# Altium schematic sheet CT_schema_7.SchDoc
size 405 x 220 mm
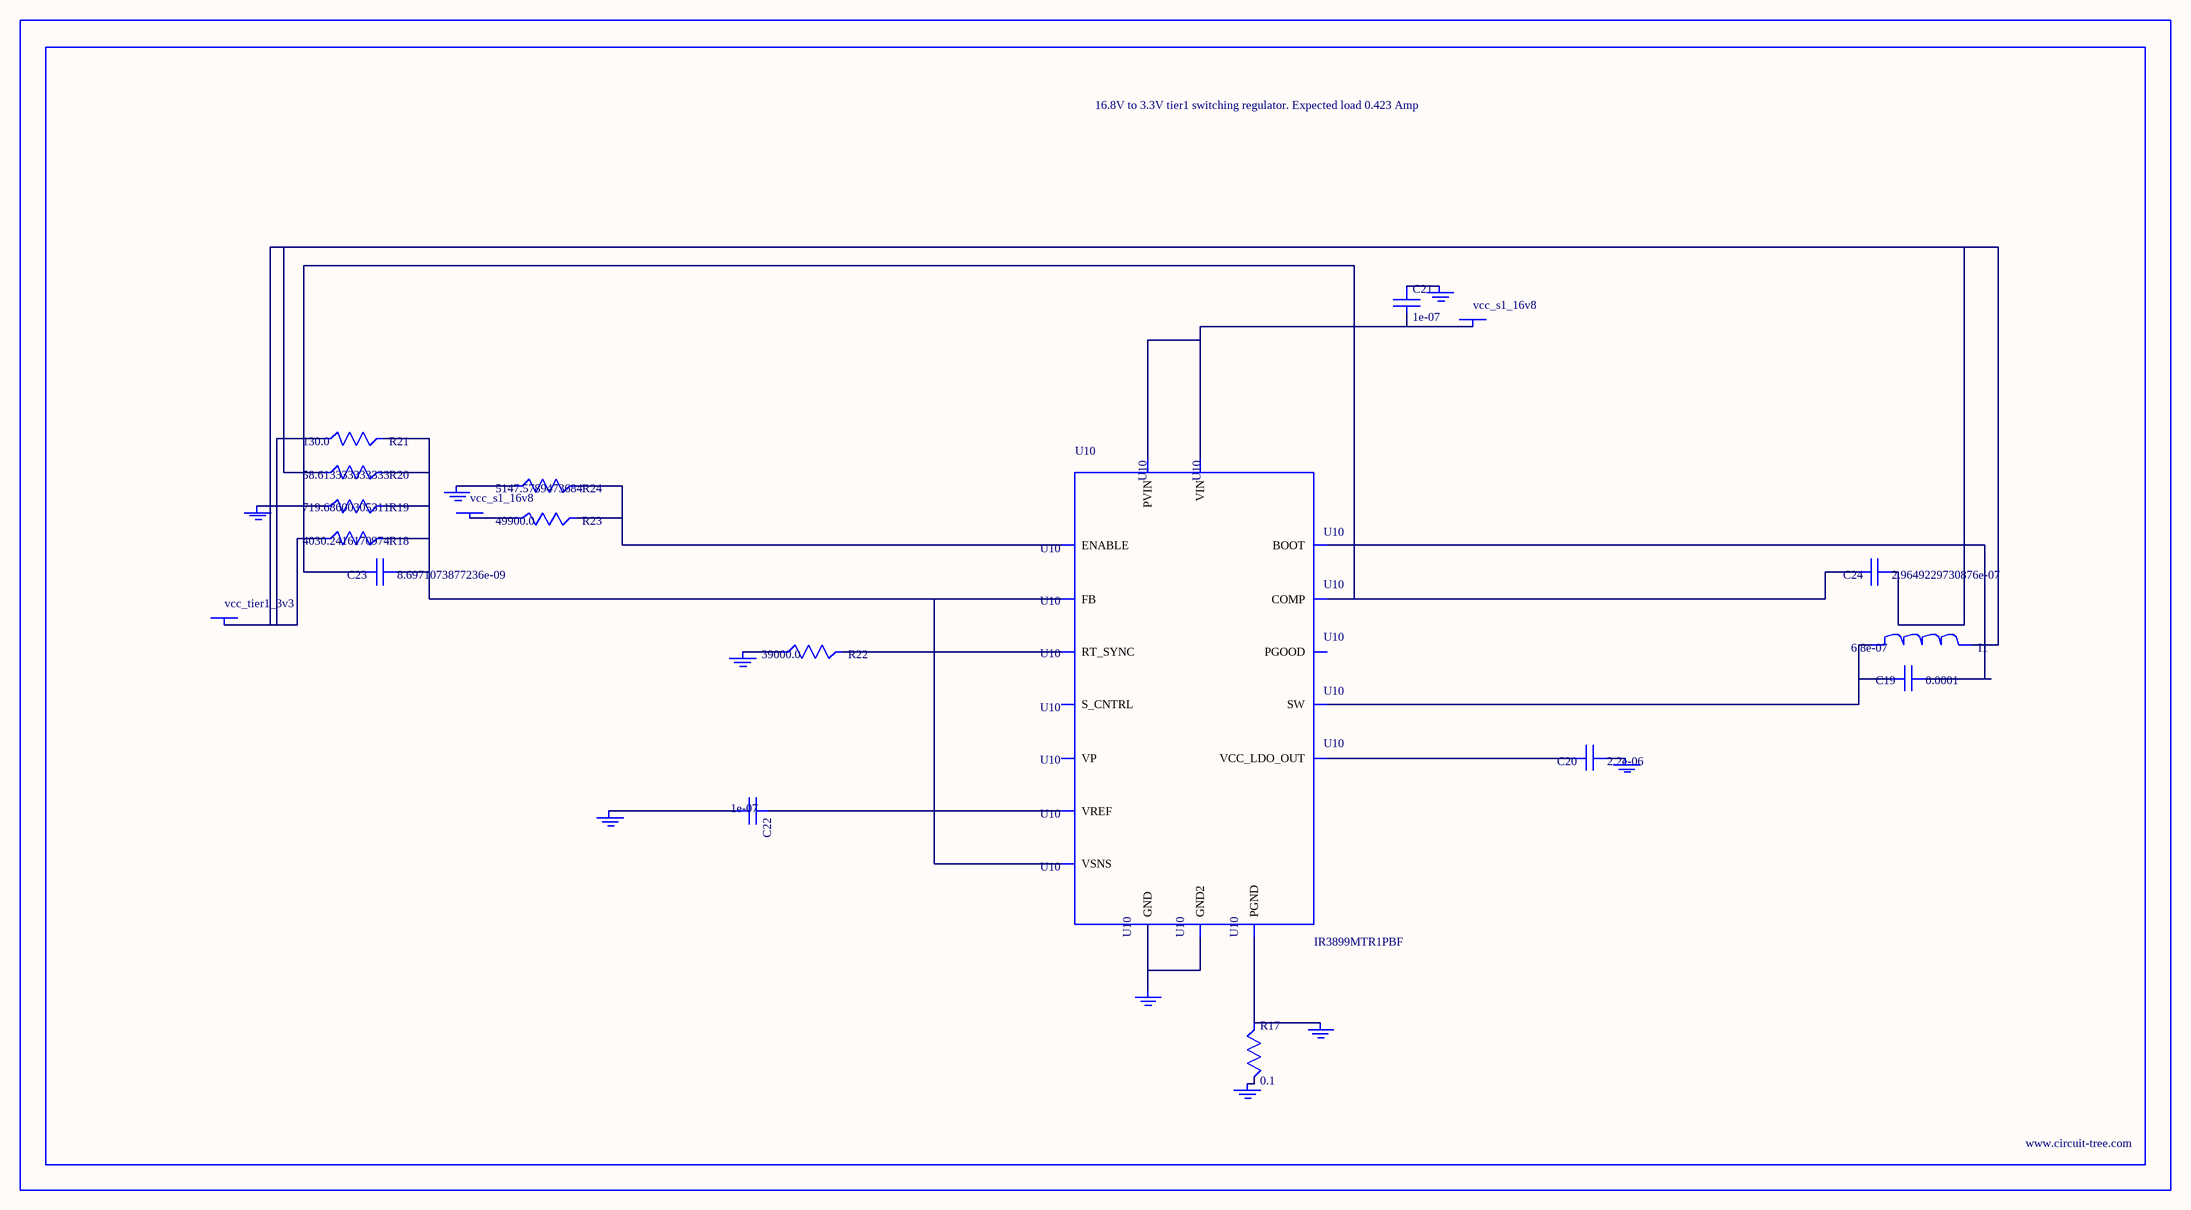
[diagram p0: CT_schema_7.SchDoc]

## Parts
BORDER6  (no value)
C19  0.0001  [C1210]
C20  2.2e-06  [C0603]
C21  1e-07  [C0402]
C22  1e-07  [C0402]
C23  8.6971073877236e-09  [R0603]
C24  2.9649229730876e-07  [R0603]
GND_INSTANCE_6_0  (no value)
GND_INSTANCE_6_1  (no value)
GND_INSTANCE_6_2  (no value)
GND_INSTANCE_6_3  (no value)
GND_INSTANCE_6_4  (no value)
GND_INSTANCE_6_5  (no value)
GND_INSTANCE_6_6  (no value)
GND_INSTANCE_6_7  (no value)
GND_INSTANCE_6_8  (no value)
I1  6.8e-07  [IND25X25CZ]
POWER_INSTANCE_6_0  vcc_s1_16v8
POWER_INSTANCE_6_1  vcc_s1_16v8
POWER_INSTANCE_6_2  vcc_tier1_3v3
R17  0.1  [R0603]
R18  4030.2416170974  [R0603]
R19  719.68600305311  [R0603]
R20  58.613333333333  [R0603]
R21  130.0  [R0603]
R22  39000.0  [R0603]
R23  49900.0  [R0603]
R24  5147.5789473684  [R0603]
U10  IR3899MTR1PBF  [IR3899MTR1PBF]

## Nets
NetC19_1: C19.1 U10.14(BOOT)
NetC19_2: C19.2 I1.1 U10.12(SW)
NetC20_1: C20.1 GND_INSTANCE_6_4.0(GND)
NetC20_2: C20.2 U10.10(VCC_LDO_OUT)
NetC21_1: C21.1 GND_INSTANCE_6_3.0(GND)
NetC21_2: C21.2 POWER_INSTANCE_6_0.0(PWR) U10.9(VIN) U10.13(PVIN)
NetC22_1: C22.1 U10.2(VREF)
NetC22_2: C22.2 GND_INSTANCE_6_1.0(GND)
NetC23_1: C23.1 R18.2 R19.2 R20.2 R21.2 U10.1(FB) U10.8(VSNS)
NetC23_2: C23.2 C24.2 U10.3(COMP)
NetC24_1: C24.1 I1.2 POWER_INSTANCE_6_2.0(PWR) R18.1 R20.1 R21.1
NetGND_INSTANCE_6_0_0: GND_INSTANCE_6_0.0(GND) R19.1
NetGND_INSTANCE_6_2_0: GND_INSTANCE_6_2.0(GND) R22.1
NetGND_INSTANCE_6_5_0: GND_INSTANCE_6_5.0(GND) R17.2
NetGND_INSTANCE_6_6_0: GND_INSTANCE_6_6.0(GND) R17.1 U10.11(PGND)
NetGND_INSTANCE_6_7_0: GND_INSTANCE_6_7.0(GND) R24.1
NetGND_INSTANCE_6_8_0: GND_INSTANCE_6_8.0(GND) U10.4(GND) U10.17(GND2)
NetPOWER_INSTANCE_6_1_0: POWER_INSTANCE_6_1.0(PWR) R23.1
NetR22_2: R22.2 U10.5(RT_SYNC)
NetR23_2: R23.2 R24.2 U10.15(ENABLE)

Not connected (* = marked no-connect by the designer): U10 6(S_CNTRL) 7(PGOOD) 16(VP)

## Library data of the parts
BORDER6 = BORDER_PAGE6
C19 = GRM32ER61A107ME20L
C20 = C0603C225K8RACTU
C21 C22 = C0402C104K3RACTU
C23 = C23
C24 = C24
GND_INSTANCE_6_0-GND_INSTANCE_6_8 = GND
I1 = IHLP2525CZERR68M01
POWER_INSTANCE_6_0-POWER_INSTANCE_6_2 = PWR
R17 = ERJ-3RSFR10V
R18 = R18
R19 = R19
R20 = R20
R21 = RC0603JR-07130RL
R22 = RC0603JR-0739KL
R23 = RC0603FR-0749K9
R24 = R24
